// Mitsubishi GX Works2 project: 23.3组数据模式选择（BMOV指令）   PLC: FX3U/FX3UC

PROGRAM MAIN
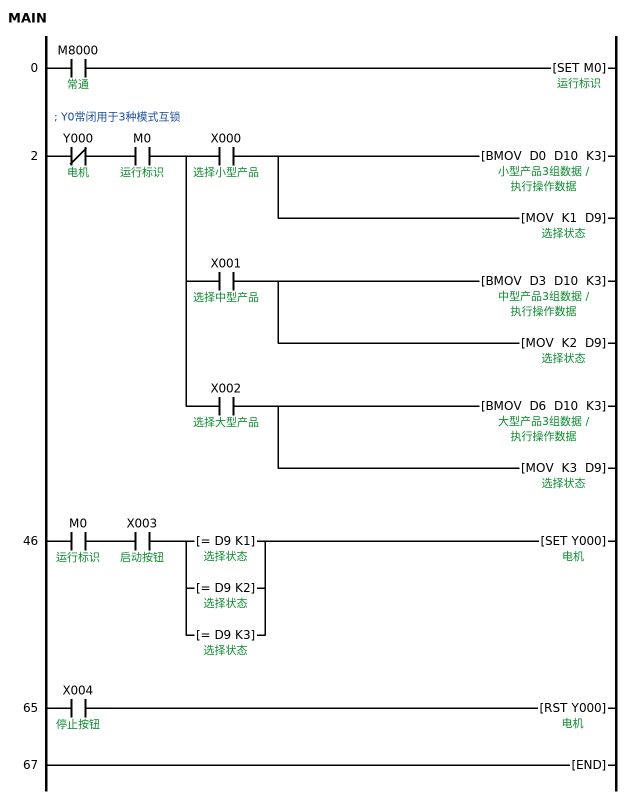
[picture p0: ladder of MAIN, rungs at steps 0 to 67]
0     LD      M8000  ; 常通
      SET     M0  ; 运行标识
; Y0常闭用于3种模式互锁
2     LDI     Y000  ; 电机
      AND     M0  ; 运行标识
      MPS
      AND     X000  ; 选择小型产品
      BMOV    D0 D10 K3  ; 小型产品3组数据 / 执行操作数据
        [note] 将小型产品3组数据寄存到D10
      MOV     K1 D9  ; 选择状态
      MRD
      AND     X001  ; 选择中型产品
      BMOV    D3 D10 K3  ; 中型产品3组数据
        [note] 将中型产品3组数据寄存到D10
      MOV     K2 D9
      MPP
      AND     X002  ; 选择大型产品
      BMOV    D6 D10 K3  ; 大型产品3组数据
        [note] 将大型产品3组数据寄存到D10
      MOV     K3 D9
46    LD      M0  ; 运行标识
      AND     X003  ; 启动按钮
      LD=     D9 K1  ; 选择状态
      OR=     D9 K2  ; 选择状态
      OR=     D9 K3  ; 选择状态
      ANB
      SET     Y000  ; 电机
65    LD      X004  ; 停止按钮
      RST     Y000  ; 电机
67    END
END_PROGRAM

// device comments not shown above
M1  ; 小型产品标识
M2  ; 中型产品标识
M3  ; 大型产品标识
